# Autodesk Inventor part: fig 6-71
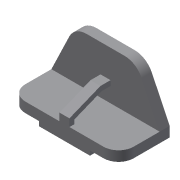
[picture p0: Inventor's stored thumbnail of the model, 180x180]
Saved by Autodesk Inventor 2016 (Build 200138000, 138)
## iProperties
Shininess: 77.0
Length Units: 11269
Angle Units: 11279
Time Units: 11290
Mass Units: 11283
Length Display Precision: 3
Angle Display Precision: 2
Created: 2001-12
Part Number: fig 6-71
Document SubType Name: Modeling
Designer: Renu Muthoo
Density: 1 g/cm^3
Material: Generic
Appearance: Default
Density: 0.0
Volumn: 0.0
Area: 0.0
PropertySet Name: Model Information
Control State: 0
Master: False
Checked Out: False
Author: Renu Muthoo
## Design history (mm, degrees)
sketch "Sketch2"
  geometry: L1 (-67.219, 19.116)-(148.781, 19.116); L2 (148.781, 19.116)-(148.781, -0.884); L3 (-67.219, -0.884)-(-67.219, 19.116); L4 (-10.219, -0.884)-(-10.219, -9.884); L5 (-10.219, -9.884)-(91.781, -9.884); L6 (91.781, -9.884)-(91.781, -0.884); L7 (148.781, -0.884)-(91.781, -0.884); L8 (-10.219, -0.884)-(-67.219, -0.884)
  constraints: 16 end point, 5 parallel, 4 perpendicular, 2 equal length, 1 horizontal
  dimensions: "d0" = 102 distance of L4.end L5.end; "d1" = 57 distance of L4.start L3.start; "d2" = 29 distance between parallel lines of L1 L5; "d3" = 20 distance of L1.end L2.end
extrude "Extrusion1" new body sketch "Sketch2" distance "d4" = 102; taper "d5" = 0 deg
sketch "Sketch3"
  geometry: L1 (67.219, -19.116)-(-148.781, -19.116) reference; L2 (67.219, -19.116)-(31.475, -93.564); L3 (-2.781, -115.116)-(-78.781, -115.116); L4 (-113.038, -93.564)-(-148.781, -19.116); A1 r 38 centre (-2.781, -77.116) between (-2.781, -115.116) and (31.475, -93.564); A2 r 38 centre (-78.781, -77.116) between (-113.038, -93.564) and (-78.781, -115.116)
  constraints: 6 end point, 4 point on circle, 4 tangent, 2 centre point, 1 equal length, 1 equal radius, 1 parallel
  dimensions: "d6" = 96 distance between parallel lines of L3 L1; "d7" = 38 radius of A1; "d8" = 76 distance of A2.centre A1.centre
extrude "Extrusion2" join sketch "Sketch3" distance "d9" = 20; taper "d10" = 0 deg
fillet "Fillet1" dims "d11" = 30
workplane "Work Plane1"
sketch "Sketch7"
  geometry: L1 (0, -82)-(-15, -82); L2 (-15, -82)-(-40, -20); L3 (-40, -20)-(-40, 0); L4 (0, -82)-(20, -82) reference; L5 (0, 0)-(-74.447, 0) reference
  constraints: 6 end point, 2 point on line, 1 horizontal, 1 perpendicular
  dimensions: "d32" = 20 distance of L2.end L3.end; "d33" = 15 distance of L1.start L1.end; "d34" = 40 distance of L5.start L3.end
feature "Rib4" sketch "Sketch7" dims "d55" = 10, "d56" = 20, "d57" = 0
body "Solid1"
other parameters: "d12" = -108
